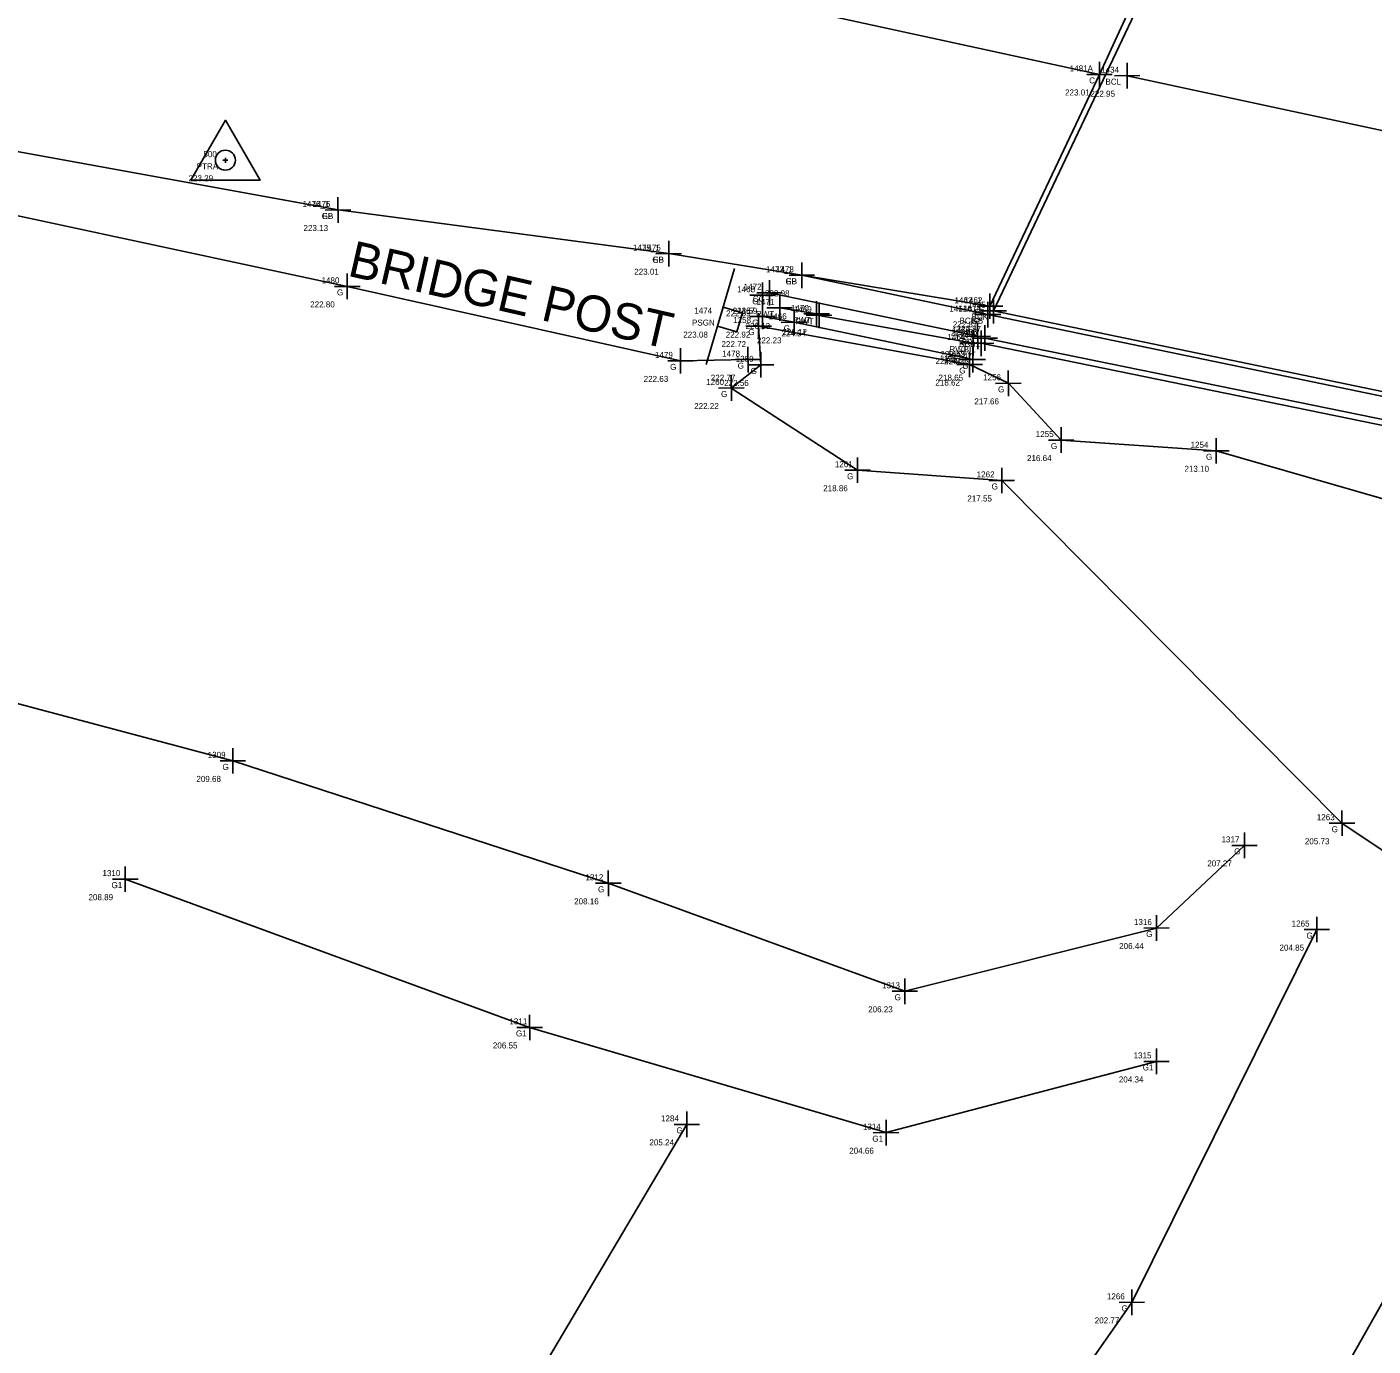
# Model space of a CAD drawing. Extents: x 1155460 to 1157069, y 590691 to 591363.
# Drawn here: x 1156014.7 to 1156081.9, y 591088.9 to 591154.7 of the extents above; entities that cross this region are included whole.
import ezdxf

# ---------------------------------------------------------------- set-up
doc = ezdxf.new("R2010")
doc.units = 0
for name, color, linetype in [('Default', 7, 'Continuous'), ('S_Bridge_Centerline', 7, 'Continuous'), ('S_Bridge_Curb', 7, 'Continuous'), ('S_Bridge_Deck', 7, 'Continuous'), ('S_Bridge_Rail', 7, 'Continuous'), ('S_Control_Traverse_Point', 7, 'Continuous'), ('S_Curb_Type_2', 7, 'Continuous'), ('S_Field_Code', 7, 'Continuous'), ('S_Ground_Elevation', 7, 'Continuous'), ('S_Ground_LevelString', 7, 'Continuous'), ('S_Guardrail_Beam', 7, 'Continuous'), ('S_Point_Elevation', 7, 'Continuous'), ('S_Point_Name', 7, 'Continuous'), ('S_RetWall_Top', 7, 'Continuous'), ('S_Roadway_Centerline', 7, 'Continuous'), ('S_Roadway_Edge_Pavement', 7, 'Continuous'), ('S_Survey_Shot', 7, 'Continuous'), ('S_Text', 7, 'Continuous'), ('S_Traffic_Sign_SinglePost', 7, 'Continuous')]:
    doc.layers.add(name, color=color, linetype=linetype)

msp = doc.modelspace()

# ---------------------------------------------------------------- linework, layer by layer
at = {"layer": 'Default'}
msp.add_line((1156049.341, 591140.24), (1156049.341, 591140.24), dxfattribs=at)
at = {"layer": 'S_Bridge_Centerline'}
msp.add_lwpolyline([(1156069.638, 591152.262), (1156118.314, 591141.802), (1156176.755, 591129.671), (1156219.832, 591120.821)], dxfattribs=at)
at = {"layer": 'S_Bridge_Curb'}
for points in [[(1156215.406, 591108.888), (1156173.426, 591117.429), (1156114, 591129.694), (1156062.688, 591140.34)], [(1156062.535, 591139.168), (1156112.353, 591128.99)]]:
    msp.add_lwpolyline(points, dxfattribs=at)
at = {"layer": 'S_Bridge_Deck'}
msp.add_lwpolyline([(1156226.576, 591133.311), (1156183.626, 591142.22), (1156124.495, 591154.361), (1156074.386, 591164.613), (1156062.974, 591140.528), (1156113.209, 591130.104), (1156172.043, 591118.153), (1156215.204, 591109.156)], close=True, dxfattribs=at)
at = {"layer": 'S_Bridge_Rail'}
msp.add_lwpolyline([(1156062.352, 591138.906), (1156112.03, 591128.733)], dxfattribs=at)
at = {"layer": 'S_Control_Traverse_Point'}
for p, q in [((1156024.649, 591148.17), (1156024.649, 591147.92)), ((1156024.524, 591148.045), (1156024.774, 591148.045))]:
    msp.add_line(p, q, dxfattribs=at)
msp.add_lwpolyline([(1156022.921, 591147.047), (1156026.378, 591147.047), (1156024.649, 591150.041)], close=True, dxfattribs=at)
msp.add_circle((1156024.649, 591148.045), 0.499, dxfattribs=at)
at = {"layer": 'S_Curb_Type_2'}
msp.add_lwpolyline([(1156062.178, 591139.257), (1156051.792, 591141.43)], dxfattribs=at)
at = {"layer": 'S_Ground_Elevation'}
for points in [[(1156050.719, 591138.093), (1156047.353, 591138.031), (1156030.73, 591141.748), (1156006.082, 591147.034), (1155959.149, 591156.139), (1155914.302, 591165.807), (1155866.781, 591175.381), (1155818.798, 591185.004), (1155782.683, 591191.68), (1155742.551, 591197.618), (1155718.267, 591200.132), (1155705.374, 591200.505), (1155676.339, 591195.263), (1155664.629, 591191.157), (1155627.328, 591184.993), (1155605.839, 591181.107), (1155578.131, 591173.993), (1155564.809, 591171.755), (1155542.767, 591145.528)], [(1155646.074, 591183.695), (1155667.285, 591185.839), (1155685.181, 591189.619), (1155702.345, 591192.555), (1155725.238, 591189.058), (1155752.984, 591181.334), (1155779.966, 591174.044), (1155813.574, 591165.635), (1155848.133, 591157.305), (1155883.485, 591149.935), (1155920.954, 591142.574), (1155967.092, 591131.69), (1155995.799, 591125.84), (1156025.021, 591118.072), (1156043.752, 591111.962), (1156058.548, 591106.575), (1156071.1, 591109.731), (1156075.486, 591113.854)], [(1155996.643, 590951.673), (1156013.684, 590979.892), (1156028.132, 590998.943), (1156048.679, 591035.507), (1156066.085, 591064.882), (1156078.36, 591083.958), (1156092.802, 591109.496), (1156104.685, 591127.907), (1156107.986, 591129.505), (1156116.297, 591145.013), (1156120.538, 591153.801)], [(1156061.934, 591138.094), (1156053.016, 591139.955), (1156051.448, 591140.241), (1156051.45, 591141.303)], [(1156098.697, 591128.011), (1156086.854, 591129.869), (1156074.081, 591133.544), (1156066.346, 591134.079), (1156063.708, 591136.91), (1156061.775, 591137.85), (1156051.25, 591139.767), (1156051.365, 591137.831), (1156049.888, 591136.677), (1156056.179, 591132.575), (1156063.385, 591132.064), (1156080.352, 591114.96), (1156085.103, 591111.78)], [(1156019.654, 591112.17), (1156039.828, 591104.771), (1156057.607, 591099.519), (1156071.097, 591103.074)], [(1156079.096, 591109.654), (1156069.869, 591091.051), (1156049.354, 591061.701), (1156024.145, 591028.368), (1156003.474, 591005.21), (1155997.751, 590999.716), (1155995.741, 590992.995), (1155973.402, 590965.465), (1155960.191, 590949.763), (1155939.135, 590909.932)], [(1155922.002, 590916.613), (1155948.186, 590955.431), (1155977.981, 590992.342), (1156009.418, 591040.16), (1156030.388, 591070.733), (1156047.666, 591099.933)]]:
    msp.add_lwpolyline(points, dxfattribs=at)
at = {"layer": 'S_Ground_LevelString'}
msp.add_line((1156062.789, 591140.757), (1156062.789, 591140.757), dxfattribs=at)
for points in [[(1156073.966, 591164.714), (1156068.256, 591152.323)], [(1156062.789, 591140.757), (1156068.256, 591152.323)]]:
    msp.add_lwpolyline(points, dxfattribs=at)
at = {"layer": 'S_Guardrail_Beam'}
for p, q in [((1156030.268, 591145.561), (1156008.288, 591149.558)), ((1156046.764, 591143.381), (1156030.268, 591145.561)), ((1156053.403, 591142.302), (1156046.764, 591143.381)), ((1156062.688, 591140.34), (1156053.403, 591142.302))]:
    msp.add_line(p, q, dxfattribs=at)
at = {"layer": 'S_RetWall_Top'}
msp.add_lwpolyline([(1156061.953, 591138.922), (1156054.267, 591140.302), (1156054.144, 591140.372), (1156052.303, 591140.671)], dxfattribs=at)
at = {"layer": 'S_Roadway_Centerline'}
msp.add_line((1156068.256, 591152.323), (1156012.449, 591164.476), dxfattribs=at)
at = {"layer": 'S_Roadway_Edge_Pavement'}
for p, q in [((1156030.268, 591145.561), (1156008.288, 591149.558)), ((1156046.764, 591143.381), (1156030.268, 591145.561)), ((1156053.403, 591142.302), (1156046.764, 591143.381)), ((1156062.789, 591140.757), (1156053.403, 591142.302))]:
    msp.add_line(p, q, dxfattribs=at)
at = {"layer": 'S_Survey_Shot'}
for p, q in [((1156068.257, 591151.687), (1156068.255, 591152.96)), ((1156069.64, 591151.625), (1156069.637, 591152.898)), ((1156067.62, 591152.322), (1156068.892, 591152.325)), ((1156068.256, 591152.323), (1156068.256, 591152.323)), ((1156069.002, 591152.26), (1156070.275, 591152.263)), ((1156069.638, 591152.262), (1156069.638, 591152.262)), ((1156030.269, 591144.924), (1156030.266, 591146.197)), ((1156030.269, 591144.924), (1156030.266, 591146.197)), ((1156029.632, 591145.559), (1156030.904, 591145.562)), ((1156029.632, 591145.559), (1156030.904, 591145.562)), ((1156030.268, 591145.561), (1156030.268, 591145.561)), ((1156030.268, 591145.561), (1156030.268, 591145.561)), ((1156046.766, 591142.745), (1156046.763, 591144.018)), ((1156046.766, 591142.745), (1156046.763, 591144.018)), ((1156046.128, 591143.38), (1156047.401, 591143.383)), ((1156046.128, 591143.38), (1156047.401, 591143.383)), ((1156046.764, 591143.381), (1156046.764, 591143.381)), ((1156046.764, 591143.381), (1156046.764, 591143.381)), ((1156053.404, 591141.666), (1156053.401, 591142.938)), ((1156053.404, 591141.666), (1156053.401, 591142.938)), ((1156030.731, 591141.111), (1156030.728, 591142.384)), ((1156052.766, 591142.3), (1156054.039, 591142.303)), ((1156052.766, 591142.3), (1156054.039, 591142.303)), ((1156053.403, 591142.302), (1156053.403, 591142.302)), ((1156053.403, 591142.302), (1156053.403, 591142.302)), ((1156030.093, 591141.746), (1156031.366, 591141.749)), ((1156030.73, 591141.748), (1156030.73, 591141.748)), ((1156051.155, 591141.429), (1156052.428, 591141.432)), ((1156051.451, 591140.667), (1156051.448, 591141.939)), ((1156051.793, 591140.794), (1156051.79, 591142.066)), ((1156051.792, 591141.43), (1156051.792, 591141.43)), ((1156050.814, 591141.302), (1156052.086, 591141.305)), ((1156051.449, 591139.605), (1156051.447, 591140.877)), ((1156051.45, 591141.303), (1156051.45, 591141.303)), ((1156052.305, 591140.035), (1156052.302, 591141.307)), ((1156054.145, 591139.736), (1156054.142, 591141.008)), ((1156054.268, 591139.666), (1156054.265, 591140.939)), ((1156062.153, 591140.756), (1156063.425, 591140.759)), ((1156062.153, 591140.756), (1156063.425, 591140.759)), ((1156062.69, 591139.704), (1156062.687, 591140.977)), ((1156062.69, 591139.704), (1156062.687, 591140.977)), ((1156062.791, 591140.121), (1156062.788, 591141.394)), ((1156062.791, 591140.121), (1156062.788, 591141.394)), ((1156062.789, 591140.757), (1156062.789, 591140.757)), ((1156062.789, 591140.757), (1156062.789, 591140.757)), ((1156062.975, 591139.892), (1156062.973, 591141.164)), ((1156050.812, 591140.24), (1156052.084, 591140.242)), ((1156051.252, 591139.131), (1156051.249, 591140.404)), ((1156051.448, 591140.241), (1156051.448, 591140.241)), ((1156051.667, 591140.67), (1156052.94, 591140.673)), ((1156052.303, 591140.671), (1156052.303, 591140.671)), ((1156053.017, 591139.318), (1156053.015, 591140.591)), ((1156053.507, 591140.371), (1156054.78, 591140.373)), ((1156053.63, 591140.301), (1156054.903, 591140.304)), ((1156054.144, 591140.372), (1156054.144, 591140.372)), ((1156054.267, 591140.302), (1156054.267, 591140.302)), ((1156062.052, 591140.339), (1156063.325, 591140.342)), ((1156062.052, 591140.339), (1156063.325, 591140.342)), ((1156062.338, 591140.527), (1156063.61, 591140.529)), ((1156062.688, 591140.34), (1156062.688, 591140.34)), ((1156062.688, 591140.34), (1156062.688, 591140.34)), ((1156062.974, 591140.528), (1156062.974, 591140.528)), ((1156050.614, 591139.766), (1156051.887, 591139.769)), ((1156051.25, 591139.767), (1156051.25, 591139.767)), ((1156052.38, 591139.953), (1156053.652, 591139.956)), ((1156053.016, 591139.955), (1156053.016, 591139.955)), ((1156061.954, 591138.286), (1156061.952, 591139.558)), ((1156062.179, 591138.621), (1156062.176, 591139.893)), ((1156062.353, 591138.269), (1156062.351, 591139.542)), ((1156062.537, 591138.532), (1156062.534, 591139.805)), ((1156050.721, 591137.456), (1156050.718, 591138.729)), ((1156061.317, 591138.921), (1156062.589, 591138.923)), ((1156061.542, 591139.255), (1156062.814, 591139.258)), ((1156061.716, 591138.904), (1156062.988, 591138.907)), ((1156061.899, 591139.167), (1156063.171, 591139.17)), ((1156061.935, 591137.458), (1156061.932, 591138.73)), ((1156061.953, 591138.922), (1156061.953, 591138.922)), ((1156062.178, 591139.257), (1156062.178, 591139.257)), ((1156062.352, 591138.906), (1156062.352, 591138.906)), ((1156062.535, 591139.168), (1156062.535, 591139.168)), ((1156047.354, 591137.395), (1156047.351, 591138.667)), ((1156050.083, 591138.091), (1156051.356, 591138.094)), ((1156050.719, 591138.093), (1156050.719, 591138.093)), ((1156051.367, 591137.195), (1156051.364, 591138.468)), ((1156061.297, 591138.092), (1156062.57, 591138.095)), ((1156061.777, 591137.214), (1156061.774, 591138.486)), ((1156061.934, 591138.094), (1156061.934, 591138.094)), ((1156046.717, 591138.03), (1156047.989, 591138.032)), ((1156047.353, 591138.031), (1156047.353, 591138.031)), ((1156050.729, 591137.83), (1156052.002, 591137.833)), ((1156051.365, 591137.831), (1156051.365, 591137.831)), ((1156061.139, 591137.849), (1156062.411, 591137.851)), ((1156061.775, 591137.85), (1156061.775, 591137.85)), ((1156063.709, 591136.273), (1156063.707, 591137.546)), ((1156049.89, 591136.041), (1156049.887, 591137.314)), ((1156063.072, 591136.908), (1156064.344, 591136.911)), ((1156063.708, 591136.91), (1156063.708, 591136.91)), ((1156049.252, 591136.676), (1156050.524, 591136.679)), ((1156049.888, 591136.677), (1156049.888, 591136.677)), ((1156066.347, 591133.443), (1156066.344, 591134.715)), ((1156065.71, 591134.078), (1156066.982, 591134.081)), ((1156066.346, 591134.079), (1156066.346, 591134.079)), ((1156074.082, 591132.908), (1156074.08, 591134.18)), ((1156073.445, 591133.542), (1156074.717, 591133.545)), ((1156074.081, 591133.544), (1156074.081, 591133.544)), ((1156056.181, 591131.939), (1156056.178, 591133.212)), ((1156063.386, 591131.428), (1156063.384, 591132.701)), ((1156055.543, 591132.574), (1156056.816, 591132.577)), ((1156056.179, 591132.575), (1156056.179, 591132.575)), ((1156062.749, 591132.063), (1156064.021, 591132.066)), ((1156063.385, 591132.064), (1156063.385, 591132.064)), ((1156025.023, 591117.436), (1156025.02, 591118.709)), ((1156024.385, 591118.071), (1156025.658, 591118.074)), ((1156025.021, 591118.072), (1156025.021, 591118.072)), ((1156080.353, 591114.324), (1156080.35, 591115.596)), ((1156079.715, 591114.959), (1156080.988, 591114.961)), ((1156080.352, 591114.96), (1156080.352, 591114.96)), ((1156075.488, 591113.218), (1156075.485, 591114.49)), ((1156074.85, 591113.853), (1156076.123, 591113.855)), ((1156075.486, 591113.854), (1156075.486, 591113.854)), ((1156019.656, 591111.534), (1156019.653, 591112.806)), ((1156043.753, 591111.326), (1156043.751, 591112.598)), ((1156019.018, 591112.168), (1156020.291, 591112.171)), ((1156019.654, 591112.17), (1156019.654, 591112.17)), ((1156043.116, 591111.961), (1156044.388, 591111.963)), ((1156043.752, 591111.962), (1156043.752, 591111.962)), ((1156071.102, 591109.094), (1156071.099, 591110.367)), ((1156079.097, 591109.018), (1156079.095, 591110.291)), ((1156070.464, 591109.729), (1156071.737, 591109.732)), ((1156071.1, 591109.731), (1156071.1, 591109.731)), ((1156078.46, 591109.653), (1156079.732, 591109.656)), ((1156079.096, 591109.654), (1156079.096, 591109.654)), ((1156058.549, 591105.939), (1156058.546, 591107.212)), ((1156057.911, 591106.574), (1156059.184, 591106.577)), ((1156058.548, 591106.575), (1156058.548, 591106.575)), ((1156039.83, 591104.135), (1156039.827, 591105.407)), ((1156039.192, 591104.77), (1156040.465, 591104.773)), ((1156039.828, 591104.771), (1156039.828, 591104.771)), ((1156071.099, 591102.438), (1156071.096, 591103.711)), ((1156070.461, 591103.073), (1156071.734, 591103.076)), ((1156071.097, 591103.074), (1156071.097, 591103.074)), ((1156047.667, 591099.297), (1156047.664, 591100.569)), ((1156047.03, 591099.931), (1156048.302, 591099.934)), ((1156047.666, 591099.933), (1156047.666, 591099.933)), ((1156057.608, 591098.882), (1156057.606, 591100.155)), ((1156056.971, 591099.517), (1156058.243, 591099.52)), ((1156057.607, 591099.519), (1156057.607, 591099.519)), ((1156069.232, 591091.05), (1156070.505, 591091.053)), ((1156069.87, 591090.415), (1156069.867, 591091.688)), ((1156069.869, 591091.051), (1156069.869, 591091.051))]:
    msp.add_line(p, q, dxfattribs=at)
at = {"layer": 'S_Traffic_Sign_SinglePost'}
msp.add_line((1156048.629, 591137.849), (1156050.052, 591142.632), dxfattribs=at)
msp.add_lwpolyline([(1156049.198, 591139.762), (1156049.483, 591140.718), (1156050.439, 591140.434), (1156050.155, 591139.477)], close=True, dxfattribs=at)

# ---------------------------------------------------------------- texts
at = {"layer": 'S_Field_Code'}
for s, p in [('C', (1156067.741, 591151.873)), ('BCL', (1156068.552, 591151.812)), ('PTRA', (1156023.218, 591147.595)), ('GB', (1156029.453, 591145.111)), ('EP', (1156029.481, 591145.111)), ('GB', (1156045.949, 591142.931)), ('EP', (1156045.978, 591142.931)), ('GB', (1156052.588, 591141.852)), ('EP', (1156052.616, 591141.852)), ('G', (1156030.215, 591141.297)), ('G', (1156050.935, 591140.853)), ('CC', (1156050.962, 591140.98)), ('PSGN', (1156047.926, 591139.79)), ('G', (1156050.933, 591139.791)), ('RWT', (1156051.118, 591140.221)), ('RWT', (1156052.958, 591139.922)), ('RWT', (1156053.081, 591139.852)), ('BCB2', (1156061.274, 591139.89)), ('GB', (1156061.874, 591139.89)), ('BDK', (1156061.873, 591140.078)), ('EP', (1156062.003, 591140.307)), ('L2', (1156062.017, 591140.307)), ('G', (1156050.735, 591139.317)), ('G', (1156052.501, 591139.505)), ('RWT', (1156060.767, 591138.472)), ('BCB1', (1156061.25, 591138.718)), ('CC', (1156061.349, 591138.807)), ('BIL', (1156061.48, 591138.456)), ('G', (1156046.838, 591137.581)), ('G', (1156050.205, 591137.643)), ('G', (1156050.85, 591137.381)), ('G', (1156061.26, 591137.4)), ('G', (1156061.419, 591137.644)), ('G', (1156063.193, 591136.46)), ('G', (1156049.373, 591136.227)), ('G', (1156065.831, 591133.629)), ('G', (1156073.566, 591133.094)), ('G', (1156055.664, 591132.125)), ('G', (1156062.87, 591131.614)), ('G', (1156024.506, 591117.622)), ('G', (1156079.837, 591114.51)), ('G', (1156074.971, 591113.404)), ('G1', (1156018.969, 591111.72)), ('G', (1156043.237, 591111.512)), ('G', (1156070.586, 591109.281)), ('G', (1156078.581, 591109.204)), ('G', (1156058.033, 591106.125)), ('G1', (1156039.144, 591104.321)), ('G1', (1156070.412, 591102.624)), ('G', (1156047.151, 591099.483)), ('G1', (1156056.922, 591099.069)), ('G', (1156069.354, 591090.601))]:
    msp.add_text(s, height=0.3, dxfattribs=at).set_placement(p)
at = {"layer": 'S_Point_Elevation'}
for s, p in [('223.01', (1156066.537, 591151.273)), ('222.95', (1156067.801, 591151.212)), ('223.29', (1156022.812, 591146.995)), ('223.13', (1156028.546, 591144.511)), ('223.13', (1156028.546, 591144.511)), ('223.01', (1156045.045, 591142.331)), ('223.01', (1156045.045, 591142.331)), ('222.98', (1156051.565, 591141.252)), ('222.98', (1156051.565, 591141.252)), ('222.80', (1156028.88, 591140.698)), ('222.99', (1156049.626, 591140.253)), ('223.59', (1156049.954, 591140.38)), ('223.08', (1156047.491, 591139.19)), ('222.92', (1156049.61, 591139.191)), ('226.13', (1156050.596, 591139.621)), ('224.54', (1156052.387, 591139.252)), ('226.12', (1156052.436, 591139.322)), ('223.46', (1156060.837, 591139.29)), ('223.46', (1156060.837, 591139.29)), ('222.87', (1156060.935, 591139.707)), ('222.87', (1156060.935, 591139.707)), ('222.87', (1156061.12, 591139.478)), ('222.72', (1156049.396, 591138.717)), ('222.23', (1156051.164, 591138.905)), ('224.43', (1156060.073, 591137.872)), ('223.43', (1156060.312, 591138.207)), ('224.36', (1156060.5, 591137.856)), ('223.47', (1156060.667, 591138.118)), ('222.63', (1156045.515, 591136.981)), ('222.77', (1156048.863, 591137.043)), ('222.56', (1156049.528, 591136.781)), ('218.62', (1156060.068, 591136.8)), ('218.65', (1156060.226, 591137.044)), ('217.66', (1156062.012, 591135.86)), ('222.22', (1156048.036, 591135.627)), ('216.64', (1156064.638, 591133.029)), ('213.10', (1156072.492, 591132.494)), ('218.86', (1156054.472, 591131.525)), ('217.55', (1156061.661, 591131.014)), ('209.68', (1156023.201, 591117.022)), ('205.73', (1156078.5, 591113.91)), ('207.27', (1156073.632, 591112.804)), ('208.89', (1156017.819, 591111.12)), ('208.16', (1156042.047, 591110.912)), ('206.44', (1156069.237, 591108.681)), ('204.85', (1156077.233, 591108.604)), ('206.23', (1156056.713, 591105.525)), ('206.55', (1156037.993, 591103.721)), ('204.34', (1156069.22, 591102.024)), ('205.24', (1156045.802, 591098.883)), ('204.66', (1156055.772, 591098.469)), ('202.77', (1156068.015, 591090.001))]:
    msp.add_text(s, height=0.3, dxfattribs=at).set_placement(p)
at = {"layer": 'S_Point_Name'}
for s, p in [('1481A', (1156066.77, 591152.473)), ('1434', (1156068.339, 591152.412)), ('500', (1156023.553, 591148.195)), ('1476_1', (1156028.496, 591145.711)), ('1476', (1156028.995, 591145.711)), ('1475_1', (1156044.979, 591143.531)), ('1475', (1156045.477, 591143.531)), ('1473_1', (1156051.617, 591142.452)), ('1473', (1156052.115, 591142.452)), ('1480', (1156029.447, 591141.898)), ('1468', (1156050.179, 591141.453)), ('1472', (1156050.504, 591141.58)), ('1471', (1156051.146, 591140.821)), ('1470', (1156052.859, 591140.522)), ('1469', (1156053.01, 591140.452)), ('1461A_1', (1156060.764, 591140.49)), ('1462_1', (1156061.02, 591140.907)), ('1461A', (1156061.217, 591140.49)), ('1462', (1156061.519, 591140.907)), ('1435', (1156061.689, 591140.678)), ('1474', (1156048.039, 591140.39)), ('1258', (1156049.98, 591139.917)), ('1467', (1156050.175, 591140.391)), ('1466', (1156051.759, 591140.105)), ('1463', (1156060.907, 591139.407)), ('1436', (1156061.264, 591139.318)), ('1464', (1156060.668, 591139.072)), ('1437', (1156061.065, 591139.056)), ('1479', (1156046.08, 591138.181)), ('1478', (1156049.432, 591138.243)), ('1259', (1156050.109, 591137.981)), ('1257', (1156060.502, 591138)), ('1465', (1156060.663, 591138.244)), ('1260', (1156048.634, 591136.827)), ('1256', (1156062.451, 591137.06)), ('1255', (1156065.075, 591134.229)), ('1254', (1156072.796, 591133.694)), ('1261', (1156055.053, 591132.725)), ('1262', (1156062.128, 591132.215)), ('1309', (1156023.767, 591118.222)), ('1263', (1156079.095, 591115.11)), ('1317', (1156074.343, 591114.004)), ('1310', (1156018.516, 591112.32)), ('1312', (1156042.611, 591112.112)), ('1316', (1156069.974, 591109.881)), ('1265', (1156077.84, 591109.804)), ('1313', (1156057.407, 591106.725)), ('1311', (1156038.818, 591104.921)), ('1315', (1156069.956, 591103.224)), ('1284', (1156046.381, 591100.083)), ('1314', (1156056.452, 591099.669)), ('1266', (1156068.626, 591091.201))]:
    msp.add_text(s, height=0.3, dxfattribs=at).set_placement(p)
at = {"layer": 'S_Text'}
msp.add_text('BRIDGE POST', height=1.8, rotation=347.09933, dxfattribs=at).set_placement((1156030.69, 591142.289))

doc.saveas('drawing.dxf')
